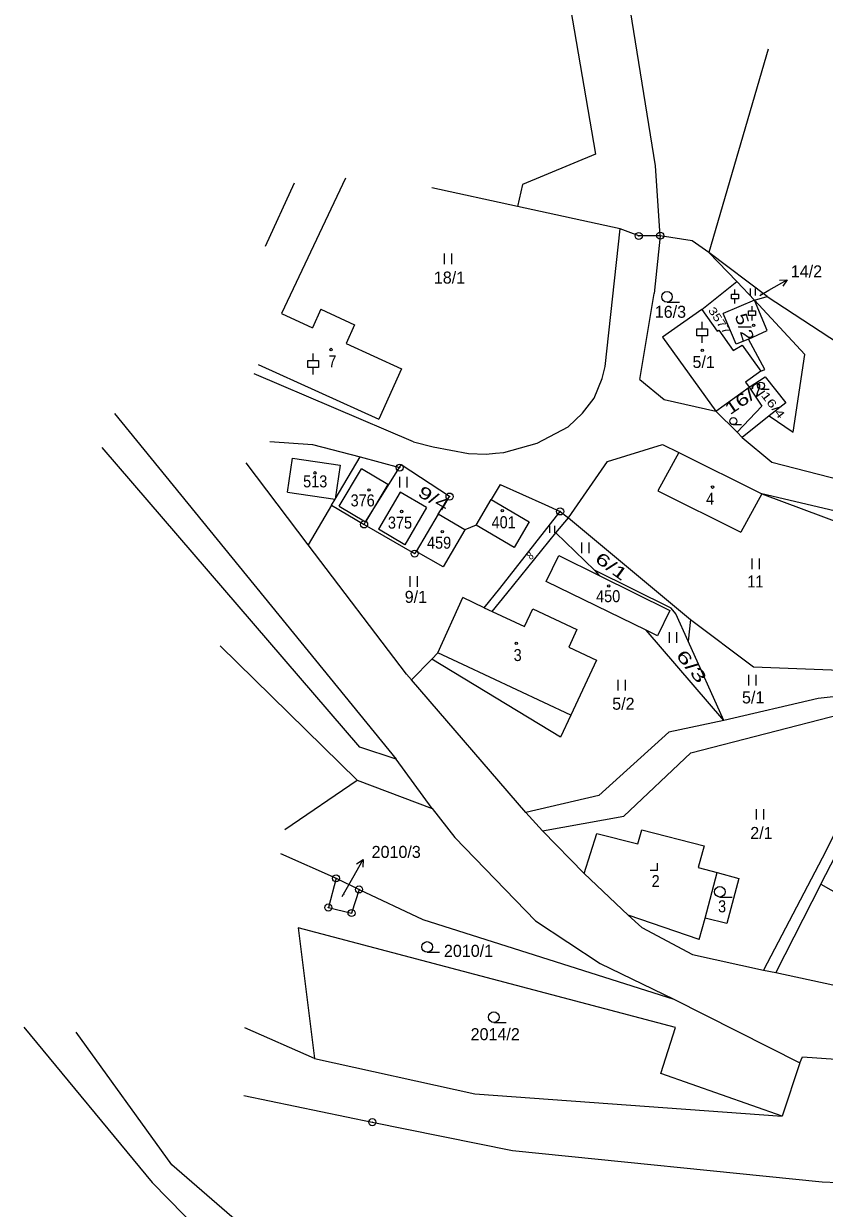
# Model space of a CAD drawing. Extents: x -665688 to -664583, y -1006118 to -1004927.
# Drawn here: x -665637.6 to -665524.4, y -1005201.6 to -1005034.2 of the extents above; entities that cross this region are included whole.
import ezdxf
from ezdxf.enums import TextEntityAlignment as Align

# ---------------------------------------------------------------- set-up
doc = ezdxf.new("R2010")
doc.units = 0
doc.header["$LTSCALE"] = 0.68
for name, color, linetype, lineweight in [('1', 7, 'Continuous', 25), ('16', 7, 'Continuous', 25), ('24', 7, 'Continuous', 25), ('25', 7, 'Continuous', 25), ('4', 7, 'Continuous', 25)]:
    doc.layers.add(name, color=color, linetype=linetype, lineweight=lineweight)
doc.layers.add('18', color=7, linetype='Continuous')
doc.layers.add('19', color=7, linetype='Continuous')

msp = doc.modelspace()

# ---------------------------------------------------------------- linework, layer by layer
at = {"layer": '1'}
for p, q in [((-665532.32, -1005037.79), (-665540.72, -1005066.52)), ((-665599.34, -1005056.73), (-665603.44, -1005065.67)), ((-665567.74, -1005060), (-665579.87, -1005057.36)), ((-665553.25, -1005063.16), (-665567.74, -1005060)), ((-665547.58, -1005064.14), (-665548.46, -1005072.32)), ((-665532.44, -1005072.72), (-665540.72, -1005066.52)), ((-665550.46, -1005084.49), (-665548.46, -1005072.32)), ((-665534.23, -1005073.27), (-665538.66, -1005075.12)), ((-665534.23, -1005073.27), (-665532.44, -1005072.72)), ((-665532.44, -1005072.72), (-665521.14, -1005080.12)), ((-665595.55, -1005074.55), (-665596.75, -1005077.18)), ((-665595.55, -1005074.55), (-665590.81, -1005076.74)), ((-665536.84, -1005079.48), (-665538.66, -1005075.12)), ((-665590.81, -1005076.74), (-665592, -1005079.37)), ((-665535.1, -1005078.76), (-665536.84, -1005079.48)), ((-665592, -1005079.37), (-665584.18, -1005082.97)), ((-665604.41, -1005082.35), (-665587.37, -1005090.1)), ((-665528.79, -1005091.93), (-665527.15, -1005080.93)), ((-665582.45, -1005093.28), (-665604.98, -1005083.69)), ((-665584.18, -1005082.97), (-665587.37, -1005090.1)), ((-665550.46, -1005084.49), (-665547.02, -1005087.31)), ((-665535.53, -1005084.83), (-665535.01, -1005085.57)), ((-665535.01, -1005085.57), (-665532.75, -1005084.09)), ((-665532.75, -1005084.09), (-665529.82, -1005087.76)), ((-665547.02, -1005087.31), (-665539.74, -1005088.94)), ((-665533.23, -1005088.22), (-665536.71, -1005091.93)), ((-665624.74, -1005089.28), (-665584.91, -1005138.14)), ((-665532.19, -1005089.6), (-665528.79, -1005091.93)), ((-665590.07, -1005136.42), (-665626.51, -1005094.06)), ((-665602.77, -1005093.23), (-665596.74, -1005093.65)), ((-665596.74, -1005093.65), (-665590, -1005095.4)), ((-665600.27, -1005100.39), (-665599.57, -1005095.6)), ((-665599.57, -1005095.6), (-665592.83, -1005096.58)), ((-665593.53, -1005101.37), (-665590, -1005095.4)), ((-665590, -1005095.4), (-665584.43, -1005096.93)), ((-665597.34, -1005107.82), (-665606.13, -1005096.24)), ((-665592.83, -1005096.58), (-665593.53, -1005101.37)), ((-665584.43, -1005096.93), (-665584.19, -1005096.54)), ((-665577.37, -1005101.02), (-665584.19, -1005096.54)), ((-665600.27, -1005100.39), (-665593.53, -1005101.37)), ((-665584.36, -1005100.38), (-665587.43, -1005105.65)), ((-665580.64, -1005102.55), (-665584.36, -1005100.38)), ((-665570.23, -1005099.31), (-665571.48, -1005101.44)), ((-665533.23, -1005100.65), (-665536.19, -1005106.05)), ((-665594.05, -1005102.23), (-665597.34, -1005107.82)), ((-665594.05, -1005102.23), (-665593.53, -1005101.37)), ((-665594.05, -1005102.23), (-665589.45, -1005104.96)), ((-665578.99, -1005103.51), (-665577.37, -1005101.02)), ((-665580.64, -1005102.55), (-665583.71, -1005107.82)), ((-665570.25, -1005114), (-665561.73, -1005103.12)), ((-665561.73, -1005103.12), (-665560.56, -1005104.02)), ((-665589.45, -1005104.96), (-665582.31, -1005109.08)), ((-665583.71, -1005107.82), (-665587.43, -1005105.65)), ((-665573.61, -1005105.07), (-665575.2, -1005105.72)), ((-665569.26, -1005114.72), (-665562.34, -1005106.13)), ((-665562.34, -1005106.13), (-665556.88, -1005111.4)), ((-665583.45, -1005126.11), (-665597.34, -1005107.82)), ((-665582.09, -1005108.78), (-665582.31, -1005109.08)), ((-665563.69, -1005113.02), (-665561.92, -1005109.37)), ((-665556.88, -1005111.4), (-665556.21, -1005112.18)), ((-665572.49, -1005116.73), (-665570.25, -1005114)), ((-665579.04, -1005123.13), (-665575.48, -1005115.3)), ((-665572.49, -1005116.73), (-665575.48, -1005115.3)), ((-665571.36, -1005117.26), (-665569.26, -1005114.72)), ((-665572.49, -1005116.73), (-665571.36, -1005117.26)), ((-665571.36, -1005117.26), (-665566.75, -1005119.4)), ((-665546.21, -1005117.1), (-665547.96, -1005120.69)), ((-665543.3, -1005118.41), (-665543.65, -1005121.45)), ((-665538.58, -1005132.69), (-665549.57, -1005119.91)), ((-665590.45, -1005141.12), (-665609.8, -1005122.12)), ((-665579.87, -1005123.98), (-665582.74, -1005126.93)), ((-665579.04, -1005123.13), (-665579.87, -1005123.98)), ((-665561.69, -1005135.04), (-665579.87, -1005123.98)), ((-665560.23, -1005131.91), (-665561.69, -1005135.04)), ((-665584.91, -1005138.14), (-665590.07, -1005136.42)), ((-665579.85, -1005145.1), (-665584.91, -1005138.14)), ((-665600.66, -1005148.07), (-665590.45, -1005141.12)), ((-665524.85, -1005155.81), (-665518.03, -1005142.52)), ((-665566.58, -1005145.69), (-665564.22, -1005148.26)), ((-665564.22, -1005148.26), (-665558.34, -1005154.32)), ((-665601.28, -1005151.49), (-665593.42, -1005154.98)), ((-665524.66, -1005152.15), (-665532.99, -1005167.94)), ((-665552.11, -1005160.21), (-665558.34, -1005154.32)), ((-665593.42, -1005154.98), (-665594.51, -1005159.11)), ((-665524.85, -1005155.81), (-665531.25, -1005168.29)), ((-665524.85, -1005155.81), (-665514.79, -1005161.53)), ((-665590.17, -1005156.55), (-665591.23, -1005159.89)), ((-665594.51, -1005159.11), (-665591.23, -1005159.89)), ((-665565.22, -1005160.98), (-665556.09, -1005167)), ((-665542.09, -1005163.61), (-665552.11, -1005160.21)), ((-665538.17, -1005161.38), (-665541.22, -1005160.61)), ((-665543.04, -1005165.76), (-665532.99, -1005167.94)), ((-665556.09, -1005167), (-665545.66, -1005172.05)), ((-665532.99, -1005167.94), (-665531.25, -1005168.29)), ((-665596.46, -1005180.47), (-665606.33, -1005176.12))]:
    msp.add_line(p, q, dxfattribs=at)
for points in [[(-665557.92, -1004927.31), (-665555.11, -1004930.72), (-665560.8, -1004945.13), (-665565.17, -1004959.97), (-665566.63, -1004974.13), (-665562.99, -1005016.05), (-665556.74, -1005052.64), (-665567.04, -1005056.91), (-665567.74, -1005060)], [(-665547.58, -1005064.14), (-665548.25, -1005054.26), (-665556.32, -1005004.3)], [(-665592.09, -1005055.99), (-665601.14, -1005075.16), (-665596.75, -1005077.18)], [(-665582.45, -1005093.28), (-665579.7, -1005094.01), (-665574.7, -1005094.91), (-665572.2, -1005095.01), (-665570.87, -1005094.87), (-665569.7, -1005094.8), (-665564.96, -1005093.47), (-665560.59, -1005091.16), (-665558.59, -1005089.24), (-665556.92, -1005087.09), (-665555.81, -1005084.32), (-665555.37, -1005082.62), (-665553.25, -1005063.16)], [(-665547.58, -1005064.14), (-665550.61, -1005064.18), (-665553.25, -1005063.16)], [(-665540.72, -1005066.52), (-665543.08, -1005064.87), (-665547.58, -1005064.14)], [(-665541.68, -1005074.58), (-665536.75, -1005070.64), (-665540.72, -1005066.52)], [(-665527.15, -1005080.93), (-665534.23, -1005073.27), (-665536.75, -1005070.64)], [(-665541.68, -1005074.58), (-665547.26, -1005078.5), (-665539.74, -1005088.94)], [(-665541.68, -1005074.58), (-665539.52, -1005077.65), (-665539.29, -1005077.49)], [(-665539.29, -1005077.49), (-665537.27, -1005080.37), (-665536, -1005079.61), (-665533.37, -1005083.31), (-665535.53, -1005084.83)], [(-665533.37, -1005083.31), (-665532.81, -1005083.05), (-665535.1, -1005078.76)], [(-665539.74, -1005088.94), (-665535.01, -1005085.57), (-665533.23, -1005088.22)], [(-665535.98, -1005092.65), (-665536.71, -1005091.93), (-665539.74, -1005088.94)], [(-665529.82, -1005087.76), (-665532.19, -1005089.6), (-665535.98, -1005092.65)], [(-665560.56, -1005104.02), (-665555.06, -1005096.04), (-665547.27, -1005093.64)], [(-665547.27, -1005093.64), (-665544.94, -1005094.79), (-665547.9, -1005100.19), (-665536.19, -1005106.05)], [(-665535.98, -1005092.65), (-665531.82, -1005096.14), (-665503.75, -1005103.38)], [(-665544.94, -1005094.79), (-665533.23, -1005100.65), (-665505.02, -1005111.13), (-665511.14, -1005125.96)], [(-665589.45, -1005104.96), (-665589.24, -1005104.61), (-665584.43, -1005096.93)], [(-665570.23, -1005099.31), (-665563.89, -1005102.16), (-665561.73, -1005103.12)], [(-665505.02, -1005111.13), (-665503.92, -1005107.53), (-665533.23, -1005100.65)], [(-665575.2, -1005105.72), (-665578.99, -1005103.51), (-665582.09, -1005108.78)], [(-665562.34, -1005106.13), (-665560.56, -1005104.02), (-665543.3, -1005118.41)], [(-665575.2, -1005105.72), (-665578.29, -1005110.97), (-665582.09, -1005108.78)], [(-665561.92, -1005109.37), (-665556.21, -1005112.18), (-665546.21, -1005117.1)], [(-665538.58, -1005132.69), (-665543.65, -1005121.45), (-665545.39, -1005117.59), (-665546.05, -1005116.79), (-665556.88, -1005111.4)], [(-665547.96, -1005120.69), (-665549.57, -1005119.91), (-665563.69, -1005113.02)], [(-665566.75, -1005119.4), (-665565.59, -1005116.9), (-665559.35, -1005119.8), (-665560.52, -1005122.31), (-665556.61, -1005124.13), (-665560.23, -1005131.91)], [(-665543.3, -1005118.41), (-665534.37, -1005125.08), (-665511.14, -1005125.96), (-665514.04, -1005132.26), (-665520.11, -1005128.99), (-665525.24, -1005129.57), (-665538.58, -1005132.69)], [(-665566.58, -1005145.69), (-665582.74, -1005126.93), (-665583.45, -1005126.11)], [(-665564.22, -1005148.26), (-665552.71, -1005146.21), (-665543.25, -1005137.26), (-665522.06, -1005131.79), (-665516.57, -1005135.18)], [(-665538.58, -1005132.69), (-665546.36, -1005134.32), (-665556.25, -1005143.26), (-665566.58, -1005145.69)], [(-665516.57, -1005135.18), (-665519.49, -1005141.81), (-665524.66, -1005152.15)], [(-665590.45, -1005141.12), (-665579.85, -1005145.1), (-665576.61, -1005149.22), (-665565.22, -1005160.98)], [(-665558.34, -1005154.32), (-665556.55, -1005148.64), (-665550.74, -1005150.12), (-665550.16, -1005148.12), (-665541.38, -1005150.41), (-665542.22, -1005153.46), (-665539.54, -1005154.14)], [(-665542.09, -1005163.61), (-665541.22, -1005160.61), (-665539.54, -1005154.14)], [(-665539.54, -1005154.14), (-665536.47, -1005154.99), (-665538.17, -1005161.38)], [(-665593.42, -1005154.98), (-665590.17, -1005156.55), (-665581.14, -1005160.82), (-665545.66, -1005172.05), (-665527.86, -1005181.07), (-665527.45, -1005180.2), (-665515.99, -1005181.03), (-665490.32, -1005183.42), (-665458.39, -1005187.75), (-665437.98, -1005192.49), (-665417.3, -1005200.53), (-665399.75, -1005208.35)], [(-665552.11, -1005160.21), (-665550.2, -1005161.93), (-665543.04, -1005165.76)], [(-665527.86, -1005181.07), (-665530.34, -1005188.59), (-665547.48, -1005182.58), (-665545.43, -1005176.08), (-665598.78, -1005161.97), (-665596.46, -1005180.47), (-665573.78, -1005185.46), (-665530.34, -1005188.59)], [(-665531.25, -1005168.29), (-665510.97, -1005172.68), (-665505.84, -1005173.21)], [(-665637.59, -1005176.03), (-665619.42, -1005197.98), (-665610.34, -1005207.28), (-665593.31, -1005215.14), (-665581.94, -1005219.27)], [(-665429.85, -1005311.87), (-665474.09, -1005270.9), (-665483.93, -1005263.19), (-665503.85, -1005250.35), (-665521.76, -1005239.72), (-665538.2, -1005231.14), (-665560.7, -1005220.99), (-665592.26, -1005211.56), (-665608.15, -1005202.85), (-665616.64, -1005195.48), (-665630.18, -1005176.74)], [(-665606.44, -1005185.69), (-665588.29, -1005189.45), (-665568.47, -1005193.44), (-665524.68, -1005197.88), (-665491.46, -1005199.28), (-665463.07, -1005202.62), (-665454.32, -1005206.34), (-665437.29, -1005211.76), (-665406.05, -1005224.73)]]:
    msp.add_lwpolyline(points, dxfattribs=at)
msp.add_lwpolyline([(-665568.23, -1005108.23), (-665573.61, -1005105.07), (-665571.48, -1005101.44), (-665566.1, -1005104.57)], close=True, dxfattribs=at)
at = {"layer": '16'}
for p, q in [((-665532.22, -1005071.86), (-665529.622, -1005070.36)), ((-665533.51, -1005072.61), (-665532.22, -1005071.86)), ((-665591.06, -1005154.92), (-665589.592, -1005152.304)), ((-665592.54, -1005157.56), (-665591.06, -1005154.92))]:
    msp.add_line(p, q, dxfattribs=at)
for points in [[(-665530.738, -1005070.427), (-665529.622, -1005070.36), (-665530.238, -1005071.294)], [(-665590.518, -1005152.932), (-665589.592, -1005152.304), (-665589.646, -1005153.421)]]:
    msp.add_lwpolyline(points, dxfattribs=at)
at = {"layer": '24'}
for centre, radius in [((-665550.61, -1005064.18), 0.5), ((-665547.58, -1005064.14), 0.5), ((-665550.61, -1005064.18), 0.032), ((-665547.58, -1005064.14), 0.032), ((-665584.43, -1005096.93), 0.5), ((-665584.43, -1005096.93), 0.032), ((-665577.37, -1005101.02), 0.5), ((-665577.37, -1005101.02), 0.032), ((-665561.73, -1005103.12), 0.5), ((-665561.73, -1005103.12), 0.032), ((-665589.45, -1005104.96), 0.5), ((-665589.45, -1005104.96), 0.032), ((-665582.31, -1005109.08), 0.5), ((-665582.31, -1005109.08), 0.032), ((-665593.42, -1005154.98), 0.5), ((-665593.42, -1005154.98), 0.032), ((-665590.17, -1005156.55), 0.5), ((-665590.17, -1005156.55), 0.032), ((-665594.51, -1005159.11), 0.5), ((-665594.51, -1005159.11), 0.032), ((-665591.23, -1005159.89), 0.5), ((-665591.23, -1005159.89), 0.032), ((-665588.29, -1005189.45), 0.5), ((-665588.29, -1005189.45), 0.032)]:
    msp.add_circle(centre, radius, dxfattribs=at)
at = {"layer": '25'}
for p, q in [((-665578.097, -1005068.175), (-665578.097, -1005066.675)), ((-665577.063, -1005068.175), (-665577.063, -1005066.675)), ((-665537.01, -1005072.409), (-665537.01, -1005071.739)), ((-665534.796, -1005072.592), (-665534.796, -1005071.587)), ((-665534.103, -1005072.592), (-665534.103, -1005071.587)), ((-665546.62, -1005073.54), (-665544.87, -1005073.54)), ((-665537.01, -1005073.75), (-665537.01, -1005073.079)), ((-665534.6, -1005074.769), (-665534.6, -1005074.099)), ((-665534.6, -1005076.11), (-665534.6, -1005075.439)), ((-665541.64, -1005077.3), (-665541.64, -1005076.3)), ((-665541.64, -1005079.3), (-665541.64, -1005078.3)), ((-665596.66, -1005081.78), (-665596.66, -1005080.78)), ((-665596.66, -1005083.78), (-665596.66, -1005082.78)), ((-665533.34, -1005085.84), (-665532.167, -1005085.84)), ((-665537.25, -1005090.85), (-665536.077, -1005090.85)), ((-665584.417, -1005099.715), (-665584.417, -1005098.215)), ((-665583.383, -1005099.715), (-665583.383, -1005098.215)), ((-665563.186, -1005106.162), (-665563.186, -1005105.157)), ((-665562.493, -1005106.162), (-665562.493, -1005105.157)), ((-665558.657, -1005109.005), (-665558.657, -1005107.505)), ((-665557.623, -1005109.005), (-665557.623, -1005107.505)), ((-665534.587, -1005111.285), (-665534.587, -1005109.785)), ((-665533.553, -1005111.285), (-665533.553, -1005109.785)), ((-665582.927, -1005113.785), (-665582.927, -1005112.285)), ((-665581.893, -1005113.785), (-665581.893, -1005112.285)), ((-665546.277, -1005121.705), (-665546.277, -1005120.205)), ((-665545.243, -1005121.705), (-665545.243, -1005120.205)), ((-665553.507, -1005128.415), (-665553.507, -1005126.915)), ((-665552.473, -1005128.415), (-665552.473, -1005126.915)), ((-665535.047, -1005127.705), (-665535.047, -1005126.205)), ((-665534.013, -1005127.705), (-665534.013, -1005126.205)), ((-665533.987, -1005146.685), (-665533.987, -1005145.185)), ((-665532.953, -1005146.685), (-665532.953, -1005145.185)), ((-665539.15, -1005157.63), (-665537.4, -1005157.63)), ((-665580.53, -1005165.43), (-665578.78, -1005165.43)), ((-665571.11, -1005175.36), (-665569.36, -1005175.36))]:
    msp.add_line(p, q, dxfattribs=at)
for points in [[(-665536.507, -1005073.079), (-665537.512, -1005073.079), (-665537.512, -1005072.409), (-665536.507, -1005072.409)], [(-665534.097, -1005075.439), (-665535.102, -1005075.439), (-665535.102, -1005074.769), (-665534.097, -1005074.769)], [(-665540.89, -1005078.3), (-665542.39, -1005078.3), (-665542.39, -1005077.3), (-665540.89, -1005077.3)], [(-665595.91, -1005082.78), (-665597.41, -1005082.78), (-665597.41, -1005081.78), (-665595.91, -1005081.78)]]:
    msp.add_lwpolyline(points, close=True, dxfattribs=at)
msp.add_lwpolyline([(-665548.99, -1005153.82), (-665547.99, -1005153.82), (-665547.99, -1005152.82)], dxfattribs=at)
for centre, radius in [((-665546.62, -1005072.79), 0.75), ((-665534.37, -1005076.82), 0.175), ((-665594.13, -1005080.24), 0.175), ((-665541.64, -1005080.34), 0.175), ((-665533.3395, -1005085.3375), 0.5025), ((-665537.2495, -1005090.3475), 0.5025), ((-665596.41, -1005097.67), 0.175), ((-665588.76, -1005100.08), 0.175), ((-665540.18, -1005099.68), 0.175), ((-665584.15, -1005103.13), 0.175), ((-665569.92, -1005103), 0.175), ((-665578.4, -1005105.99), 0.175), ((-665554.86, -1005113.65), 0.175), ((-665567.94, -1005121.77), 0.175), ((-665539.15, -1005156.88), 0.75), ((-665580.53, -1005164.68), 0.75), ((-665571.11, -1005174.61), 0.75)]:
    msp.add_circle(centre, radius, dxfattribs=at)
at = {"layer": '4'}
for p, q in [((-665592.98, -1005102.39), (-665589.84, -1005097.08)), ((-665586.09, -1005099.3), (-665589.84, -1005097.08)), ((-665586.09, -1005099.3), (-665589.24, -1005104.61)), ((-665592.98, -1005102.39), (-665589.24, -1005104.61)), ((-665575.5, -1005124.77), (-665579.04, -1005123.13)), ((-665560.23, -1005131.91), (-665575.5, -1005124.77))]:
    msp.add_line(p, q, dxfattribs=at)
msp.add_lwpolyline([(-665535.1, -1005078.76), (-665532.45, -1005077.53), (-665534.23, -1005073.27)], dxfattribs=at)

# ---------------------------------------------------------------- texts
at = {"layer": '16'}
for s, p in [('14/2', (-665529.12, -1005070.04)), ('2010/3', (-665588.39, -1005152.1))]:
    msp.add_text(s, height=1.7, dxfattribs=at).set_placement(p)
at = {"layer": '18'}
for s, height, p in [('18/1', 1.7, (-665577.3795, -1005070.91)), ('14/2', 0.1, (-665533.31, -1005072.41)), ('16/3', 1.7, (-665546.1395, -1005075.75)), ('9/1', 1.7, (-665582.1295, -1005116.05)), ('5/1', 1.7, (-665534.4395, -1005130.26)), ('5/2', 1.7, (-665552.7895, -1005131.15)), ('2/1', 1.7, (-665533.2695, -1005149.42)), ('2010/3', 0.1, (-665592.3395, -1005157.36)), ('2010/1', 1.7, (-665574.6895, -1005166.08)), ('2014/2', 1.7, (-665570.9095, -1005177.86))]:
    msp.add_text(s, height=height, dxfattribs=at).set_placement(p, align=Align.CENTER)
for s, height, rotation, width, p in [('3577', 1.14, 304.002, 1.25, (-665539.6734, -1005076.4652)), ('16/2', 1.7, 34.2, 1.4, (-665535.1608, -1005087.8003)), ('16/4', 1.14, 307.702, 1.45, (-665532.0703, -1005088.4274)), ('9/4', 1.7, 330.003, 1.45, (-665580.0285, -1005102.0162)), ('8', 1.14, 37.8, 0.85, (-665565.6468, -1005109.8192)), ('6/1', 1.7, 323.903, 1.55, (-665554.9758, -1005111.5554)), ('6/3', 1.7, 308.902, 1.65, (-665543.8202, -1005125.5497))]:
    msp.add_text(s, height=height, rotation=rotation, dxfattribs=dict(at, width=width)).set_placement(p, align=Align.CENTER)
at = {"layer": '18', "width": 0.9}
for s, p in [('11', (-665534.13, -1005113.87)), ('3', (-665538.8295, -1005159.79))]:
    msp.add_text(s, height=1.7, dxfattribs=at).set_placement(p, align=Align.CENTER)
at = {"layer": '19', "width": 1.25}
msp.add_text('5/2', height=1.7, rotation=287.402, dxfattribs=at).set_placement((-665536.4661, -1005077.3158), align=Align.CENTER)
at = {"layer": '19', "width": 0.9}
for s, p in [('7', (-665593.9295, -1005082.74)), ('513', (-665596.3695, -1005099.72)), ('376', (-665589.6595, -1005102.41)), ('4', (-665540.5195, -1005102.17)), ('375', (-665584.3795, -1005105.55)), ('401', (-665569.7195, -1005105.5)), ('459', (-665578.8495, -1005108.39)), ('450', (-665554.9395, -1005115.95)), ('3', (-665567.7395, -1005124.27)), ('2', (-665548.2295, -1005156.22))]:
    msp.add_text(s, height=1.7, dxfattribs=at).set_placement(p, align=Align.CENTER)
at = {"layer": '19'}
msp.add_text('5/1', height=1.7, dxfattribs=at).set_placement((-665541.4395, -1005082.84), align=Align.CENTER)

doc.saveas('drawing.dxf')
